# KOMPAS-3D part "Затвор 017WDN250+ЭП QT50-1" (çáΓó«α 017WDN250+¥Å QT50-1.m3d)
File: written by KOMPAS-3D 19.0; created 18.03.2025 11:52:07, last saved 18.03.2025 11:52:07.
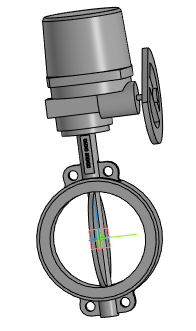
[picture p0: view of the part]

Document properties: Полное имя файла: Затвор 017WDN250+ЭП QT50-1.a3d

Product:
- Part/product: Затвор 017WDN250+ЭП QT50-1
    Масса: 105.922

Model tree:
1. Операция без истории:1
